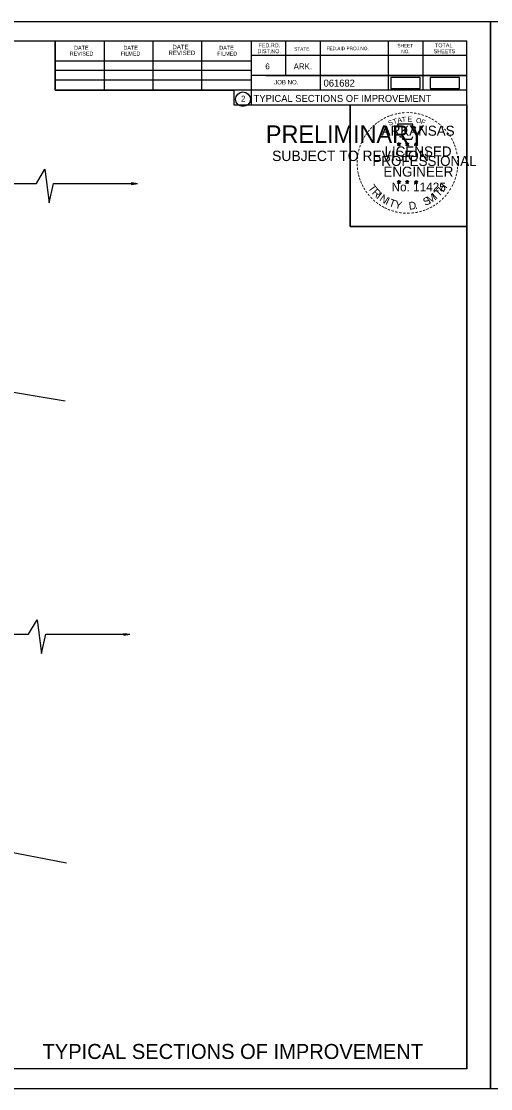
# Model space of a CAD drawing. Extents: x 1364961 to 1365294, y 367927 to 368034.
# Drawn here: x 1365080.4 to 1365127.2, y 367927.1 to 368033.8 of the extents above; entities that cross this region are included whole.
import ezdxf

# ---------------------------------------------------------------- set-up
doc = ezdxf.new("R2010")
doc.units = 0
for name, color, linetype in [('Default', 7, 'Continuous'), ('Level 26', 7, 'Continuous'), ('Level 6', 7, 'Continuous'), ('Level 8', 7, 'Continuous'), ('Level 9', 7, 'Continuous')]:
    doc.layers.add(name, color=color, linetype=linetype)

msp = doc.modelspace()

# ---------------------------------------------------------------- linework, layer by layer
at = {"layer": 'Default'}
for p, q in [((1365091.38, 368017.63), (1365091.98, 368017.54)), ((1365091.38, 368017.63), (1365091.38, 368017.45)), ((1365091.38, 368017.61), (1365091.88, 368017.54)), ((1365091.38, 368017.6), (1365091.77, 368017.54)), ((1365091.38, 368017.58), (1365091.67, 368017.54)), ((1365091.38, 368017.56), (1365091.57, 368017.54)), ((1365091.38, 368017.55), (1365091.47, 368017.54)), ((1365091.38, 368017.45), (1365091.98, 368017.54)), ((1365091.38, 368017.51), (1365091.57, 368017.54)), ((1365091.38, 368017.48), (1365091.77, 368017.54)), ((1365091.38, 368017.46), (1365091.88, 368017.54)), ((1365091.38, 368017.49), (1365091.67, 368017.54)), ((1365091.38, 368017.52), (1365091.47, 368017.54)), ((1365065.97, 367998.94), (1365084.75, 367995.83)), ((1365090.6, 367972.58), (1365091.2, 367972.49)), ((1365090.6, 367972.58), (1365090.6, 367972.4)), ((1365090.6, 367972.56), (1365091.1, 367972.49)), ((1365090.6, 367972.55), (1365090.99, 367972.49)), ((1365090.6, 367972.53), (1365090.89, 367972.49)), ((1365090.6, 367972.52), (1365090.79, 367972.49)), ((1365090.6, 367972.5), (1365090.69, 367972.49)), ((1365090.6, 367972.4), (1365091.2, 367972.49)), ((1365090.6, 367972.46), (1365090.79, 367972.49)), ((1365090.6, 367972.43), (1365090.99, 367972.49)), ((1365090.6, 367972.41), (1365091.1, 367972.49)), ((1365090.6, 367972.44), (1365090.89, 367972.49)), ((1365090.6, 367972.48), (1365090.69, 367972.49)), ((1365065.2, 367953.49), (1365084.87, 367949.65))]:
    msp.add_line(p, q, dxfattribs=at)
for points in [[(1365117.27, 368027.05), (1365120.19, 368027.05), (1365120.19, 368028.15), (1365117.27, 368028.15)], [(1365121.21, 368027.05), (1365124.12, 368027.05), (1365124.12, 368028.15), (1365121.21, 368028.15)]]:
    msp.add_lwpolyline(points, close=True, dxfattribs=at)
for points in [[(1365055.98, 368017.54), (1365081.88, 368017.54), (1365082.73, 368018.97), (1365083.16, 368015.62), (1365083.59, 368017.54), (1365091.98, 368017.54)], [(1365055.2, 367972.49), (1365081.1, 367972.49), (1365081.95, 367973.93), (1365082.38, 367970.57), (1365082.81, 367972.49), (1365091.2, 367972.49)]]:
    msp.add_lwpolyline(points, dxfattribs=at)
at = {"layer": 'Level 26'}
for p, q in [((1364960.58, 368033.75), (1365127.24, 368033.75)), ((1365112.88, 368014.17), (1365112.88, 368014.17)), ((1364960.58, 367927.09), (1365127.24, 367927.09))]:
    msp.add_line(p, q, dxfattribs=at)
for points in [[(1364960.57, 368033.75), (1365127.24, 368033.75), (1365127.24, 367927.08), (1364960.57, 367927.08)], [(1365127.24, 368033.75), (1365293.91, 368033.75), (1365293.91, 367927.08), (1365127.24, 367927.08)], [(1365083.74, 368031.8), (1365083.74, 368026.86), (1365101.6, 368026.86), (1365101.6, 368025.4), (1365113.2, 368025.4), (1365113.2, 368013.24), (1365124.87, 368013.24), (1365124.87, 367929.07), (1364966.78, 367929.07), (1364966.78, 368031.8)], [(1365113.2, 368025.42), (1365124.87, 368025.42), (1365124.87, 368013.24), (1365113.2, 368013.24)]]:
    msp.add_lwpolyline(points, close=True, dxfattribs=at)
at = {"layer": 'Level 6'}
for p, q in [((1364966.78, 368031.8), (1365124.87, 368031.8)), ((1365083.74, 368026.86), (1365083.74, 368031.8)), ((1365088.67, 368026.86), (1365088.67, 368031.7)), ((1365093.55, 368026.86), (1365093.55, 368031.7)), ((1365098.39, 368026.86), (1365098.39, 368031.7)), ((1365103.32, 368031.8), (1365103.32, 368025.4)), ((1365106.74, 368031.8), (1365106.74, 368028.33)), ((1365110.21, 368031.8), (1365110.21, 368026.86)), ((1365117, 368031.8), (1365117, 368026.86)), ((1365120.47, 368031.8), (1365120.47, 368026.86)), ((1365124.87, 367929.07), (1365124.87, 368031.8)), ((1365083.74, 368029.79), (1365103.32, 368029.79)), ((1365124.87, 368030.33), (1365103.32, 368030.33)), ((1365124.87, 368030.34), (1365124.87, 368030.34)), ((1365083.74, 368028.86), (1365103.32, 368028.86)), ((1365083.74, 368026.86), (1365083.74, 368027.89)), ((1365083.74, 368027.89), (1365103.32, 368027.89)), ((1365124.87, 368028.33), (1365103.32, 368028.33)), ((1365104.8, 368028.33), (1365124.87, 368028.33)), ((1365124.87, 368026.86), (1365083.74, 368026.86)), ((1365103.32, 368025.4), (1365124.87, 368025.4)), ((1365124.87, 367929.07), (1364966.78, 367929.07))]:
    msp.add_line(p, q, dxfattribs=at)
msp.add_circle((1365102.51, 368025.97), 0.733, dxfattribs=at)
at = {"layer": 'Level 8'}
for p, q in [((1365117.91, 368021.53), (1365118.08, 368021.47)), ((1365117.91, 368021.53), (1365118.04, 368021.51)), ((1365117.91, 368021.53), (1365118.03, 368021.47)), ((1365117.98, 368021.32), (1365118.08, 368021.47)), ((1365117.98, 368021.32), (1365118.04, 368021.45)), ((1365117.98, 368021.32), (1365118.08, 368021.43)), ((1365118.08, 368021.65), (1365118.06, 368021.53)), ((1365118.08, 368021.47), (1365118.08, 368021.65)), ((1365118.08, 368021.65), (1365118.11, 368021.53)), ((1365118.26, 368021.53), (1365118.08, 368021.47)), ((1365118.19, 368021.32), (1365118.08, 368021.47)), ((1365118.19, 368021.32), (1365118.08, 368021.43)), ((1365118.26, 368021.53), (1365118.11, 368021.5)), ((1365118.19, 368021.32), (1365118.12, 368021.47)), ((1365118.26, 368021.53), (1365118.16, 368021.48)), ((1365118.74, 368021.53), (1365118.92, 368021.47)), ((1365118.74, 368021.53), (1365118.87, 368021.51)), ((1365118.74, 368021.53), (1365118.86, 368021.47)), ((1365118.81, 368021.32), (1365118.92, 368021.47)), ((1365118.81, 368021.32), (1365118.87, 368021.45)), ((1365118.81, 368021.32), (1365118.92, 368021.43)), ((1365118.92, 368021.65), (1365118.9, 368021.53)), ((1365118.92, 368021.47), (1365118.92, 368021.65)), ((1365118.92, 368021.65), (1365118.94, 368021.53)), ((1365119.09, 368021.53), (1365118.92, 368021.47)), ((1365119.03, 368021.32), (1365118.92, 368021.47)), ((1365119.03, 368021.32), (1365118.92, 368021.43)), ((1365119.09, 368021.53), (1365118.95, 368021.5)), ((1365119.03, 368021.32), (1365118.96, 368021.47)), ((1365119.09, 368021.53), (1365118.99, 368021.48)), ((1365119.63, 368021.52), (1365119.8, 368021.47)), ((1365119.63, 368021.52), (1365119.75, 368021.5)), ((1365119.63, 368021.52), (1365119.74, 368021.46)), ((1365119.69, 368021.32), (1365119.8, 368021.47)), ((1365119.69, 368021.32), (1365119.76, 368021.44)), ((1365119.69, 368021.32), (1365119.8, 368021.43)), ((1365119.8, 368021.65), (1365119.78, 368021.52)), ((1365119.8, 368021.47), (1365119.8, 368021.65)), ((1365119.8, 368021.65), (1365119.83, 368021.52)), ((1365119.97, 368021.52), (1365119.8, 368021.47)), ((1365119.91, 368021.32), (1365119.8, 368021.47)), ((1365119.91, 368021.32), (1365119.8, 368021.42)), ((1365119.97, 368021.52), (1365119.83, 368021.5)), ((1365119.91, 368021.32), (1365119.84, 368021.46)), ((1365119.97, 368021.52), (1365119.87, 368021.47)), ((1365117.91, 368017.74), (1365118.08, 368017.69)), ((1365117.91, 368017.74), (1365118.03, 368017.72)), ((1365117.91, 368017.74), (1365118.03, 368017.68)), ((1365117.97, 368017.54), (1365118.08, 368017.69)), ((1365117.97, 368017.54), (1365118.04, 368017.66)), ((1365117.97, 368017.54), (1365118.08, 368017.65)), ((1365118.08, 368017.87), (1365118.06, 368017.74)), ((1365118.08, 368017.69), (1365118.08, 368017.87)), ((1365118.08, 368017.87), (1365118.11, 368017.74)), ((1365118.26, 368017.74), (1365118.08, 368017.69)), ((1365118.19, 368017.54), (1365118.08, 368017.69)), ((1365118.19, 368017.54), (1365118.08, 368017.64)), ((1365118.26, 368017.74), (1365118.11, 368017.72)), ((1365118.19, 368017.54), (1365118.12, 368017.68)), ((1365118.26, 368017.74), (1365118.15, 368017.69)), ((1365118.74, 368017.74), (1365118.92, 368017.69)), ((1365118.74, 368017.74), (1365118.87, 368017.72)), ((1365118.74, 368017.74), (1365118.86, 368017.68)), ((1365118.81, 368017.54), (1365118.92, 368017.69)), ((1365118.81, 368017.54), (1365118.87, 368017.66)), ((1365118.81, 368017.54), (1365118.92, 368017.65)), ((1365118.92, 368017.87), (1365118.9, 368017.74)), ((1365118.92, 368017.69), (1365118.92, 368017.87)), ((1365118.92, 368017.87), (1365118.94, 368017.74)), ((1365119.09, 368017.74), (1365118.92, 368017.69)), ((1365119.02, 368017.54), (1365118.92, 368017.69)), ((1365119.02, 368017.54), (1365118.92, 368017.64)), ((1365119.09, 368017.74), (1365118.95, 368017.72)), ((1365119.02, 368017.54), (1365118.95, 368017.68)), ((1365119.09, 368017.74), (1365118.99, 368017.69)), ((1365119.63, 368017.74), (1365119.8, 368017.68)), ((1365119.63, 368017.74), (1365119.75, 368017.71)), ((1365119.63, 368017.74), (1365119.74, 368017.68)), ((1365119.69, 368017.53), (1365119.8, 368017.68)), ((1365119.69, 368017.53), (1365119.75, 368017.65)), ((1365119.69, 368017.53), (1365119.8, 368017.64)), ((1365119.8, 368017.86), (1365119.78, 368017.74)), ((1365119.8, 368017.68), (1365119.8, 368017.86)), ((1365119.8, 368017.86), (1365119.82, 368017.74)), ((1365119.97, 368017.74), (1365119.8, 368017.68)), ((1365119.91, 368017.53), (1365119.8, 368017.68)), ((1365119.91, 368017.53), (1365119.8, 368017.64)), ((1365119.97, 368017.74), (1365119.83, 368017.71)), ((1365119.91, 368017.53), (1365119.84, 368017.68)), ((1365119.97, 368017.74), (1365119.87, 368017.69))]:
    msp.add_line(p, q, dxfattribs=at)
for points in [[(1365117.93, 368023.47), (1365118.06, 368023.05)], [(1365119.69, 368023.01), (1365119.76, 368023.15), (1365119.41, 368023.14), (1365119.49, 368023.47), (1365117.93, 368023.47)], [(1365118.08, 368021.65), (1365118.19, 368021.32), (1365117.91, 368021.53), (1365118.26, 368021.53), (1365117.98, 368021.32), (1365118.08, 368021.65)], [(1365118.18, 368022.26), (1365118.18, 368022.21), (1365118.46, 368022.2), (1365118.43, 368021.97), (1365119.37, 368021.97), (1365119.47, 368022.23)], [(1365118.92, 368021.65), (1365119.03, 368021.32), (1365118.74, 368021.53), (1365119.09, 368021.53), (1365118.81, 368021.32), (1365118.92, 368021.65)], [(1365119.8, 368021.65), (1365119.91, 368021.32), (1365119.63, 368021.52), (1365119.97, 368021.52), (1365119.69, 368021.32), (1365119.8, 368021.65)], [(1365118.08, 368017.87), (1365118.19, 368017.54), (1365117.91, 368017.74), (1365118.26, 368017.74), (1365117.97, 368017.54), (1365118.08, 368017.87)], [(1365118.92, 368017.87), (1365119.02, 368017.54), (1365118.74, 368017.74), (1365119.09, 368017.74), (1365118.81, 368017.54), (1365118.92, 368017.87)], [(1365119.8, 368017.86), (1365119.91, 368017.53), (1365119.63, 368017.74), (1365119.97, 368017.74), (1365119.69, 368017.53), (1365119.8, 368017.86)]]:
    msp.add_lwpolyline(points, dxfattribs=at)
for centre, radius in [((1365118.08, 368021.47), 0.0861), ((1365118.08, 368021.47), 0.0723), ((1365118.08, 368021.47), 0.0579), ((1365118.08, 368021.47), 0.0495), ((1365118.08, 368021.47), 0.0374), ((1365118.08, 368021.47), 0.0248), ((1365118.08, 368021.47), 0.0148), ((1365118.92, 368021.47), 0.0861), ((1365118.92, 368021.47), 0.0723), ((1365118.92, 368021.47), 0.0579), ((1365118.92, 368021.47), 0.0495), ((1365118.92, 368021.47), 0.0374), ((1365118.92, 368021.47), 0.0248), ((1365118.92, 368021.47), 0.0148), ((1365119.8, 368021.47), 0.0861), ((1365119.8, 368021.47), 0.0723), ((1365119.8, 368021.47), 0.0579), ((1365119.8, 368021.47), 0.0495), ((1365119.8, 368021.47), 0.0374), ((1365119.8, 368021.47), 0.0248), ((1365119.8, 368021.47), 0.0148), ((1365118.08, 368017.69), 0.0861), ((1365118.08, 368017.69), 0.0723), ((1365118.08, 368017.69), 0.0579), ((1365118.08, 368017.69), 0.0495), ((1365118.08, 368017.69), 0.0374), ((1365118.08, 368017.69), 0.0248), ((1365118.08, 368017.69), 0.0148), ((1365118.92, 368017.69), 0.0861), ((1365118.92, 368017.69), 0.0723), ((1365118.92, 368017.69), 0.0579), ((1365118.92, 368017.69), 0.0495), ((1365118.92, 368017.69), 0.0374), ((1365118.92, 368017.69), 0.0248), ((1365118.92, 368017.69), 0.0148), ((1365119.8, 368017.68), 0.0861), ((1365119.8, 368017.68), 0.0723), ((1365119.8, 368017.68), 0.0579), ((1365119.8, 368017.68), 0.0495), ((1365119.8, 368017.68), 0.0374), ((1365119.8, 368017.68), 0.0248), ((1365119.8, 368017.68), 0.0148)]:
    msp.add_circle(centre, radius, dxfattribs=at)

# ---------------------------------------------------------------- texts
at = {"layer": 'Level 6'}
for s, height, p in [('DATE', 0.391, (1365085.64, 368030.92)), ('DATE', 0.391, (1365090.57, 368030.92)), ('REVISED', 0.44, (1365095.07, 368030.38)), ('DATE', 0.44, (1365095.46, 368030.97)), ('DATE', 0.391, (1365100.15, 368030.92)), ('DIST.NO.', 0.391, (1365103.96, 368030.57)), ('FED.RD.', 0.391, (1365104.06, 368031.16)), ('STATE', 0.342, (1365107.62, 368030.82)), ('FED.AID PROJ.NO.', 0.342, (1365110.85, 368030.87)), ('SHEET', 0.342, (1365117.93, 368031.16)), ('NO.', 0.342, (1365118.32, 368030.57)), ('SHEETS', 0.391, (1365121.55, 368030.57)), ('TOTAL', 0.391, (1365121.69, 368031.16)), ('REVISED', 0.391, (1365085.2, 368030.33)), ('FILMED', 0.391, (1365090.28, 368030.33)), ('FILMED', 0.391, (1365099.95, 368030.33)), ('6', 0.586, (1365104.74, 368028.96)), ('ARK.', 0.586, (1365107.57, 368028.96)), ('JOB NO.', 0.44, (1365105.62, 368027.45)), ('061682', 0.7, (1365110.56, 368027.23)), ('2', 0.586, (1365102.32, 368025.73)), ('TYPICAL SECTIONS OF IMPROVEMENT', 0.7, (1365103.57, 368025.7)), ('TYPICAL SECTIONS OF IMPROVEMENT', 1.5, (1365082.49, 367930.05))]:
    msp.add_text(s, height=height, dxfattribs=at).set_placement(p)
at = {"layer": 'Level 8'}
for s, height, rotation, p in [('-', 0.8, 19.1761, (1365117.3, 368024.03)), ('-', 0.8, 13.6302, (1365117.68, 368024.15)), ('-', 0.8, 10.2193, (1365118.02, 368024.23)), ('-', 0.8, 5.8968, (1365118.38, 368024.29)), ('-', 0.8, 0.1862, (1365118.77, 368024.32)), ('-', 0.8, 357.743, (1365119.13, 368024.32)), ('-', 0.8, 352.1617, (1365119.5, 368024.29)), ('-', 0.8, 347.2049, (1365119.86, 368024.23)), ('-', 0.8, 342.3362, (1365120.18, 368024.15)), ('-', 0.8, 42.9622, (1365115.63, 368022.96)), ('-', 0.8, 38.9507, (1365115.84, 368023.17)), ('-', 0.8, 36.2317, (1365116.08, 368023.35)), ('-', 0.8, 34.0636, (1365116.37, 368023.55)), ('-', 0.8, 28.7918, (1365116.67, 368023.74)), ('-', 0.8, 24.3072, (1365116.99, 368023.9)), ('S', 0.5, 21.594, (1365117.11, 368023.31)), ('T', 0.5, 16.4036, (1365117.56, 368023.47)), ('A', 0.5, 11.2132, (1365117.98, 368023.6)), ('T', 0.5, 6.0228, (1365118.4, 368023.68)), ('E', 0.5, 0.8323, (1365118.95, 368023.73)), ('O', 0.5, 350.4515, (1365119.76, 368023.63)), ('F', 0.5, 340.0707, (1365120.23, 368023.52)), ('-', 0.8, 337.8551, (1365120.55, 368024.04)), ('-', 0.8, 334.1211, (1365120.86, 368023.91)), ('-', 0.8, 329.6409, (1365121.15, 368023.77)), ('-', 0.8, 325.8627, (1365121.47, 368023.58)), ('-', 0.8, 320.5297, (1365121.78, 368023.37)), ('-', 0.8, 58.0706, (1365114.83, 368021.93)), ('-', 0.8, 54.2325, (1365115, 368022.19)), ('-', 0.8, 50.6142, (1365115.2, 368022.48)), ('-', 0.8, 48.4231, (1365115.4, 368022.72)), ('-', 0.8, 315.5786, (1365122.08, 368023.13)), ('-', 0.8, 309.8797, (1365122.36, 368022.85)), ('-', 0.8, 306.6522, (1365122.62, 368022.55)), ('-', 0.7, 303.6753, (1365122.87, 368022.27)), ('-', 0.8, 72.3945, (1365114.44, 368021)), ('-', 0.8, 67.7743, (1365114.55, 368021.32)), ('-', 0.8, 62.8713, (1365114.68, 368021.62)), ('-', 0.8, 299.6684, (1365123.03, 368021.96)), ('-', 0.8, 294.6628, (1365123.19, 368021.66)), ('-', 0.8, 290.5728, (1365123.32, 368021.37)), ('-', 0.8, 85.1863, (1365114.24, 368019.94)), ('-', 0.8, 81.2013, (1365114.27, 368020.29)), ('-', 0.8, 75.461, (1365114.34, 368020.64)), ('-', 0.8, 285.1233, (1365123.43, 368021.08)), ('-', 0.8, 280.5493, (1365123.53, 368020.71)), ('-', 0.8, 276.5962, (1365123.61, 368020.32)), ('-', 0.8, 94.1959, (1365114.24, 368019.23)), ('-', 0.8, 89.0622, (1365114.22, 368019.59)), ('-', 0.8, 98.9479, (1365114.28, 368018.9)), ('-', 0.8, 263.5172, (1365123.65, 368019.31)), ('-', 0.8, 274.3301, (1365123.64, 368019.96)), ('-', 0.8, 269.9407, (1365123.66, 368019.65)), ('-', 0.8, 101.7149, (1365114.34, 368018.53)), ('-', 0.8, 105.4578, (1365114.42, 368018.23)), ('-', 0.8, 109.0874, (1365114.53, 368017.92)), ('-', 0.8, 252.8681, (1365123.47, 368018.29)), ('-', 0.8, 255.7626, (1365123.56, 368018.65)), ('-', 0.8, 260.9953, (1365123.62, 368018.99)), ('-', 0.8, 114.0643, (1365114.66, 368017.62)), ('-', 0.8, 115.7289, (1365114.81, 368017.31)), ('-', 0.8, 120.4471, (1365114.99, 368017.02)), ('T', 0.77, 306.0406, (1365114.96, 368017.1)), ('R', 0.77, 314.005, (1365115.34, 368016.58)), ('T', 0.77, 46.6444, (1365122.08, 368016.15)), ('H', 0.77, 54.6088, (1365122.52, 368016.62)), ('-', 0.8, 239.0712, (1365123.03, 368017.26)), ('-', 0.8, 244.6197, (1365123.23, 368017.64)), ('-', 0.8, 247.8887, (1365123.36, 368017.95)), ('-', 0.8, 125.8934, (1365115.19, 368016.74)), ('-', 0.8, 130.7181, (1365115.42, 368016.46)), ('-', 0.8, 134.2238, (1365115.68, 368016.19)), ('-', 0.8, 138.9338, (1365115.94, 368015.95)), ('I', 0.77, 321.9694, (1365115.79, 368016.11)), ('N', 0.77, 326.5002, (1365116.08, 368015.88)), ('I', 0.77, 335.3603, (1365116.68, 368015.49)), ('T', 0.77, 339.8912, (1365117.01, 368015.32)), ('S', 0.77, 26.9312, (1365120.73, 368015.29)), ('M', 0.77, 32.6563, (1365121.15, 368015.49)), ('I', 0.77, 42.1136, (1365121.8, 368015.91)), ('-', 0.8, 225.7653, (1365122.38, 368016.37)), ('-', 0.8, 231.2538, (1365122.62, 368016.65)), ('-', 0.8, 233.8452, (1365122.83, 368016.94)), ('-', 0.8, 144.6463, (1365116.22, 368015.75)), ('-', 0.8, 148.0898, (1365116.5, 368015.57)), ('-', 0.8, 151.5704, (1365116.79, 368015.4)), ('-', 0.8, 154.6002, (1365117.05, 368015.28)), ('-', 0.8, 158.5612, (1365117.36, 368015.15)), ('-', 0.8, 162.7983, (1365117.71, 368015.05)), ('Y', 0.77, 347.8556, (1365117.62, 368015.1)), ('D', 0.77, 6.3969, (1365119.11, 368014.92)), ('.', 0.77, 13.7642, (1365119.71, 368014.98)), ('-', 0.8, 195.4743, (1365120.33, 368015.1)), ('-', 0.8, 200.7184, (1365120.67, 368015.22)), ('-', 0.8, 204.2516, (1365120.98, 368015.35)), ('-', 0.8, 207.3568, (1365121.29, 368015.51)), ('-', 0.8, 212.2491, (1365121.57, 368015.69)), ('-', 0.8, 215.7363, (1365121.84, 368015.88)), ('-', 0.8, 221.0851, (1365122.12, 368016.12)), ('-', 0.8, 167.5555, (1365118.07, 368014.96)), ('-', 0.8, 173.1155, (1365118.45, 368014.91)), ('-', 0.8, 176.5183, (1365118.83, 368014.88)), ('-', 0.8, 181.5918, (1365119.2, 368014.89)), ('-', 0.8, 185.8167, (1365119.6, 368014.93)), ('-', 0.8, 191.2858, (1365119.97, 368015))]:
    msp.add_text(s, height=height, rotation=rotation, dxfattribs=at).set_placement(p)
for s, height, p in [('ARKANSAS', 1, (1365116.36, 368022.32)), ('LICENSED', 1, (1365116.65, 368020.25)), ('DWB', 0.005, (1365118.08, 368021.47)), ('DWB', 0.005, (1365118.91, 368021.47)), ('DWB', 0.005, (1365119.79, 368021.46)), ('PROFESSIONAL', 1, (1365115.44, 368019.3)), ('ENGINEER', 1, (1365116.54, 368018.23)), ('No. 11425', 0.878, (1365117.35, 368016.76)), ('DWB', 0.005, (1365118.08, 368017.68)), ('DWB', 0.005, (1365118.91, 368017.68)), ('DWB', 0.005, (1365119.79, 368017.68))]:
    msp.add_text(s, height=height, dxfattribs=at).set_placement(p)
at = {"layer": 'Level 9'}
for s, height, p in [('DWB', 0.005, (1365104.89, 368022.53)), ('PRELIMINARY', 1.75, (1365104.79, 368021.6)), ('SUBJECT TO REVISION', 1.0376, (1365105.42, 368019.79))]:
    msp.add_text(s, height=height, dxfattribs=at).set_placement(p)

doc.saveas('drawing.dxf')
